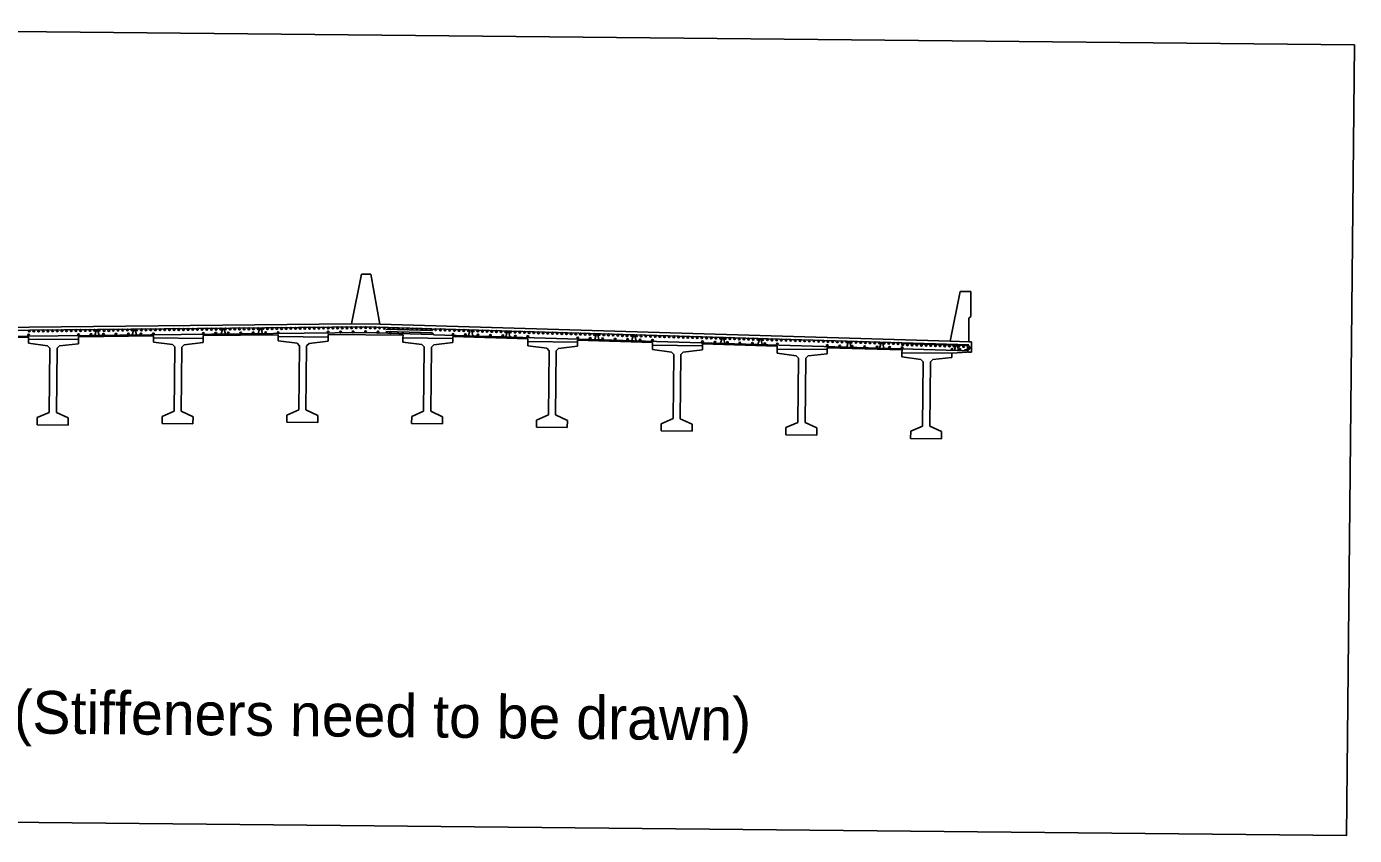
# Model space of a CAD drawing. Extents: x 632228 to 632434, y 378391 to 382112.
# Drawn here: x 632303.6 to 632396.7, y 378390.6 to 378447.3 of the extents above; entities that cross this region are included whole.
import ezdxf

# ---------------------------------------------------------------- set-up
doc = ezdxf.new("R2010")
doc.units = 0
for name, color, linetype in [('B_Boring Annot', 7, 'Continuous'), ('R_Border_Divider', 7, 'Continuous'), ('R_Border_Scale', 7, 'Continuous'), ('USACE_Easement', 7, 'Continuous')]:
    doc.layers.add(name, color=color, linetype=linetype)

msp = doc.modelspace()

# ---------------------------------------------------------------- linework, layer by layer
at = {"layer": 'B_Boring Annot'}
for p, q in [((632326.34, 378426.46), (632327.042, 378429.953)), ((632327.042, 378429.953), (632327.708, 378429.947)), ((632327.708, 378429.947), (632327.042, 378429.953)), ((632328.34, 378426.44), (632327.708, 378429.947)), ((632369.032, 378428.736), (632368.33, 378425.242)), ((632369.782, 378428.728), (632369.032, 378428.736)), ((632369.764, 378426.978), (632369.782, 378428.728)), ((632326.34, 378426.46), (632286.334, 378426.058)), ((632328.34, 378426.44), (632368.33, 378425.242)), ((632369.622, 378425.204), (632369.638, 378426.855)), ((632369.764, 378426.978), (632369.638, 378426.855)), ((632303.705, 378425.524), (632298.454, 378425.471)), ((632303.705, 378425.524), (632303.704, 378425.392)), ((632307.206, 378425.559), (632307.204, 378425.358)), ((632312.456, 378425.612), (632307.206, 378425.559)), ((632312.452, 378425.189), (632312.455, 378425.48)), ((632312.456, 378425.612), (632312.455, 378425.48)), ((632312.455, 378425.48), (632315.955, 378425.446)), ((632315.957, 378425.647), (632315.955, 378425.446)), ((632321.208, 378425.7), (632315.957, 378425.647)), ((632321.203, 378425.277), (632321.206, 378425.568)), ((632321.206, 378425.568), (632321.208, 378425.7)), ((632321.206, 378425.568), (632324.706, 378425.534)), ((632324.706, 378425.534), (632321.206, 378425.568)), ((632324.706, 378425.534), (632324.703, 378425.242)), ((632324.708, 378425.71), (632324.706, 378425.534)), ((632324.708, 378425.71), (632329.958, 378425.658)), ((632329.956, 378425.481), (632329.953, 378425.19)), ((632329.958, 378425.658), (632329.956, 378425.481)), ((632333.456, 378425.447), (632329.956, 378425.481)), ((632329.956, 378425.481), (632333.456, 378425.447)), ((632333.456, 378425.447), (632333.457, 378425.578)), ((632333.457, 378425.578), (632338.706, 378425.421)), ((632303.701, 378425.101), (632303.704, 378425.392)), ((632305.032, 378424.921), (632303.701, 378425.101)), ((632303.704, 378425.392), (632307.204, 378425.358)), ((632305.197, 378424.752), (632305.032, 378424.921)), ((632305.153, 378420.253), (632305.197, 378424.752)), ((632305.697, 378424.748), (632305.653, 378420.248)), ((632305.866, 378424.913), (632305.697, 378424.748)), ((632307.201, 378425.066), (632305.866, 378424.913)), ((632307.204, 378425.358), (632307.201, 378425.066)), ((632313.784, 378425.009), (632312.452, 378425.189)), ((632313.949, 378424.84), (632313.784, 378425.009)), ((632313.904, 378420.341), (632313.949, 378424.84)), ((632314.449, 378424.836), (632314.404, 378420.336)), ((632314.617, 378425.001), (632314.449, 378424.836)), ((632315.952, 378425.154), (632314.617, 378425.001)), ((632315.955, 378425.446), (632315.952, 378425.154)), ((632322.535, 378425.097), (632321.203, 378425.277)), ((632322.7, 378424.928), (632322.535, 378425.097)), ((632322.655, 378420.429), (632322.7, 378424.928)), ((632323.2, 378424.924), (632323.155, 378420.424)), ((632323.368, 378425.089), (632323.2, 378424.924)), ((632324.703, 378425.242), (632323.368, 378425.089)), ((632329.953, 378425.19), (632331.285, 378425.01)), ((632331.285, 378425.01), (632331.45, 378424.841)), ((632331.45, 378424.841), (632331.405, 378420.342)), ((632331.905, 378420.337), (632331.95, 378424.837)), ((632331.95, 378424.837), (632332.118, 378425.002)), ((632332.118, 378425.002), (632333.453, 378425.155)), ((632333.453, 378425.155), (632333.456, 378425.447)), ((632338.704, 378425.219), (632338.701, 378424.928)), ((632338.701, 378424.928), (632340.032, 378424.748)), ((632338.706, 378425.421), (632338.704, 378425.219)), ((632342.204, 378425.185), (632338.704, 378425.219)), ((632340.032, 378424.748), (632340.197, 378424.579)), ((632340.197, 378424.579), (632340.153, 378420.08)), ((632340.653, 378420.075), (632340.697, 378424.575)), ((632340.697, 378424.575), (632340.866, 378424.74)), ((632340.866, 378424.74), (632342.201, 378424.893)), ((632342.201, 378424.893), (632342.204, 378425.185)), ((632342.205, 378425.316), (632342.204, 378425.185)), ((632342.205, 378425.316), (632347.454, 378425.159)), ((632347.452, 378424.957), (632347.449, 378424.666)), ((632347.449, 378424.666), (632348.78, 378424.486)), ((632347.454, 378425.159), (632347.452, 378424.957)), ((632350.951, 378424.923), (632347.452, 378424.957)), ((632349.614, 378424.478), (632350.948, 378424.631)), ((632350.948, 378424.631), (632350.951, 378424.923)), ((632350.953, 378425.054), (632350.951, 378424.923)), ((632350.953, 378425.054), (632356.201, 378424.897)), ((632356.199, 378424.695), (632356.196, 378424.404)), ((632356.201, 378424.897), (632356.199, 378424.695)), ((632359.699, 378424.661), (632356.199, 378424.695)), ((632359.696, 378424.369), (632359.699, 378424.661)), ((632359.7, 378424.792), (632359.699, 378424.661)), ((632359.7, 378424.792), (632364.949, 378424.635)), ((632364.949, 378424.635), (632364.947, 378424.433)), ((632369.622, 378425.204), (632369.83, 378425.198)), ((632369.83, 378425.198), (632369.823, 378424.489)), ((632348.78, 378424.486), (632348.945, 378424.318)), ((632348.945, 378424.318), (632348.9, 378419.818)), ((632349.4, 378419.813), (632349.445, 378424.313)), ((632349.445, 378424.313), (632349.614, 378424.478)), ((632356.196, 378424.404), (632357.528, 378424.224)), ((632357.528, 378424.224), (632357.693, 378424.056)), ((632357.693, 378424.056), (632357.648, 378419.556)), ((632358.148, 378419.551), (632358.193, 378424.051)), ((632358.193, 378424.051), (632358.361, 378424.216)), ((632358.361, 378424.216), (632359.696, 378424.369)), ((632364.947, 378424.433), (632364.944, 378424.142)), ((632364.944, 378424.142), (632366.276, 378423.962)), ((632368.447, 378424.399), (632364.947, 378424.433)), ((632366.276, 378423.962), (632366.441, 378423.794)), ((632366.441, 378423.794), (632366.396, 378419.294)), ((632366.896, 378419.289), (632366.941, 378423.789)), ((632366.941, 378423.789), (632367.109, 378423.954)), ((632367.109, 378423.954), (632368.444, 378424.107)), ((632368.444, 378424.107), (632368.447, 378424.399)), ((632368.447, 378424.399), (632369.537, 378424.47)), ((632369.537, 378424.47), (632369.573, 378424.515)), ((632369.622, 378424.476), (632369.573, 378424.515)), ((632369.622, 378424.476), (632369.823, 378424.489)), ((632304.311, 378419.386), (632304.316, 378419.886)), ((632304.316, 378419.886), (632305.153, 378420.253)), ((632305.653, 378420.248), (632306.482, 378419.864)), ((632306.482, 378419.864), (632306.477, 378419.364)), ((632313.062, 378419.474), (632313.067, 378419.974)), ((632313.067, 378419.974), (632313.904, 378420.341)), ((632314.404, 378420.336), (632315.234, 378419.952)), ((632315.234, 378419.952), (632315.229, 378419.452)), ((632321.813, 378419.562), (632321.818, 378420.062)), ((632321.818, 378420.062), (632322.655, 378420.429)), ((632323.155, 378420.424), (632323.985, 378420.04)), ((632323.985, 378420.04), (632323.98, 378419.54)), ((632330.568, 378419.975), (632330.563, 378419.475)), ((632331.405, 378420.342), (632330.568, 378419.975)), ((632332.734, 378419.953), (632331.905, 378420.337)), ((632332.729, 378419.453), (632332.734, 378419.953)), ((632340.153, 378420.08), (632339.316, 378419.713)), ((632341.482, 378419.691), (632340.653, 378420.075)), ((632306.477, 378419.364), (632304.311, 378419.386)), ((632315.229, 378419.452), (632313.062, 378419.474)), ((632323.98, 378419.54), (632321.813, 378419.562)), ((632330.563, 378419.475), (632332.729, 378419.453)), ((632339.316, 378419.713), (632339.311, 378419.213)), ((632339.311, 378419.213), (632341.477, 378419.192)), ((632341.477, 378419.192), (632341.482, 378419.691)), ((632348.063, 378419.451), (632348.059, 378418.951)), ((632348.059, 378418.951), (632350.225, 378418.93)), ((632348.9, 378419.818), (632348.063, 378419.451)), ((632350.23, 378419.43), (632349.4, 378419.813)), ((632350.225, 378418.93), (632350.23, 378419.43)), ((632356.811, 378419.189), (632356.806, 378418.689)), ((632357.648, 378419.556), (632356.811, 378419.189)), ((632358.978, 378419.168), (632358.148, 378419.551)), ((632358.973, 378418.668), (632358.978, 378419.168)), ((632366.396, 378419.294), (632365.559, 378418.927)), ((632367.726, 378418.906), (632366.896, 378419.289)), ((632356.806, 378418.689), (632358.973, 378418.668)), ((632365.559, 378418.927), (632365.554, 378418.427)), ((632365.554, 378418.427), (632367.721, 378418.406)), ((632367.721, 378418.406), (632367.726, 378418.906))]:
    msp.add_line(p, q, dxfattribs=at)
at = {"layer": 'R_Border_Divider'}
for p, q in [((632326.34, 378426.46), (632328.34, 378426.44)), ((632368.33, 378425.242), (632369.622, 378425.204))]:
    msp.add_line(p, q, dxfattribs=at)
at = {"layer": 'R_Border_Scale'}
for p, q in [((632285.03, 378425.837), (632327.339, 378426.262)), ((632285.038, 378425.42), (632327.334, 378425.845)), ((632308.468, 378426.072), (632308.36, 378425.654)), ((632308.542, 378426.073), (632308.657, 378425.657)), ((632311.074, 378426.099), (632310.966, 378425.68)), ((632311.148, 378426.099), (632311.264, 378425.683)), ((632317.313, 378426.161), (632317.205, 378425.743)), ((632317.387, 378426.162), (632317.502, 378425.746)), ((632319.921, 378426.188), (632319.813, 378425.769)), ((632319.995, 378426.188), (632320.111, 378425.772)), ((632332, 378425.705), (632327.334, 378425.845)), ((632332.004, 378426.122), (632327.339, 378426.262)), ((632332.001, 378425.83), (632328.752, 378425.928)), ((632332.003, 378425.997), (632328.754, 378426.095)), ((632332.001, 378425.83), (632332.122, 378425.702)), ((632332.003, 378425.997), (632332.131, 378426.119)), ((632369.614, 378424.579), (632332.122, 378425.702)), ((632369.63, 378424.996), (632332.131, 378426.119)), ((632334.679, 378426.042), (632334.555, 378425.629)), ((632334.753, 378426.04), (632334.852, 378425.62)), ((632337.286, 378425.964), (632337.162, 378425.551)), ((632337.36, 378425.962), (632337.46, 378425.542)), ((632343.523, 378425.777), (632343.399, 378425.364)), ((632343.597, 378425.775), (632343.696, 378425.355)), ((632346.128, 378425.699), (632346.004, 378425.286)), ((632346.202, 378425.697), (632346.301, 378425.277)), ((632352.353, 378425.513), (632352.229, 378425.099)), ((632352.427, 378425.511), (632352.527, 378425.091)), ((632354.968, 378425.435), (632354.844, 378425.021)), ((632355.042, 378425.432), (632355.141, 378425.012)), ((632361.199, 378425.248), (632361.075, 378424.835)), ((632361.273, 378425.246), (632361.372, 378424.826)), ((632363.504, 378425.179), (632363.38, 378424.766)), ((632363.578, 378425.177), (632363.678, 378424.757)), ((632369.573, 378424.936), (632364.897, 378425.075)), ((632368.742, 378425.022), (632368.618, 378424.609)), ((632368.816, 378425.02), (632368.915, 378424.6)), ((632369.564, 378424.643), (632369.335, 378424.65))]:
    msp.add_line(p, q, dxfattribs=at)
for centre in [(632303.703, 378425.67), (632303.75, 378425.962), (632304.076, 378425.966), (632304.404, 378425.969), (632304.733, 378425.972), (632305.059, 378425.976), (632305.387, 378425.979), (632305.716, 378425.982), (632306.042, 378425.986), (632306.37, 378425.989), (632306.698, 378425.992), (632307.022, 378425.995), (632307.206, 378425.705), (632307.35, 378425.999), (632307.681, 378426.002), (632308.008, 378426.005), (632308.079, 378425.714), (632308.335, 378426.009), (632308.664, 378426.012), (632308.954, 378425.723), (632309, 378425.993), (632309.327, 378425.996), (632309.647, 378426.022), (632309.829, 378425.732), (632309.973, 378426.025), (632310.301, 378426.028), (632310.63, 378426.032), (632310.704, 378425.74), (632310.956, 378426.035), (632311.284, 378426.038), (632311.579, 378425.749), (632311.613, 378426.041), (632311.939, 378426.045), (632312.267, 378426.048), (632312.454, 378425.758), (632312.595, 378426.051), (632312.922, 378426.055), (632313.249, 378426.058), (632313.578, 378426.061), (632313.905, 378426.065), (632314.232, 378426.068), (632314.561, 378426.071), (632314.888, 378426.074), (632315.215, 378426.078), (632315.544, 378426.081), (632315.87, 378426.084), (632315.957, 378425.793), (632316.198, 378426.088), (632316.527, 378426.091), (632316.831, 378425.802), (632316.853, 378426.094), (632317.181, 378426.098), (632317.51, 378426.101), (632317.706, 378425.811), (632317.836, 378426.104), (632318.164, 378426.107), (632318.493, 378426.111), (632318.581, 378425.82), (632318.819, 378426.114), (632319.147, 378426.117), (632319.455, 378425.828), (632319.471, 378426.121), (632319.798, 378426.124), (632320.125, 378426.127), (632320.33, 378425.837), (632320.458, 378426.13), (632320.785, 378426.134), (632321.112, 378426.137), (632321.205, 378425.846), (632321.441, 378426.14), (632321.765, 378426.144), (632322.093, 378426.147), (632322.424, 378426.15), (632322.75, 378426.154), (632323.078, 378426.157), (632323.407, 378426.16), (632323.733, 378426.163), (632324.061, 378426.167), (632324.39, 378426.17), (632324.71, 378425.881), (632324.716, 378426.173), (632325.044, 378426.177), (632325.372, 378426.18), (632325.584, 378425.89), (632325.699, 378426.183), (632326.026, 378426.186), (632326.355, 378426.19), (632326.459, 378425.899), (632326.682, 378426.193), (632327.009, 378426.196), (632327.334, 378425.908), (632327.338, 378426.2), (632327.666, 378426.19), (632327.994, 378426.18), (632328.211, 378425.881), (632328.32, 378426.17), (632328.649, 378426.16), (632328.976, 378426.151), (632329.085, 378425.855), (632329.303, 378426.141), (632329.631, 378426.131), (632329.959, 378426.121), (632329.959, 378425.829), (632330.285, 378426.111), (632330.614, 378426.102), (632330.941, 378426.092), (632331.267, 378426.082), (632331.596, 378426.072), (632331.924, 378426.062), (632332.25, 378426.053), (632332.581, 378426.043), (632332.909, 378426.033), (632333.232, 378426.023), (632333.462, 378425.724), (632333.561, 378426.013), (632333.888, 378426.003), (632334.215, 378425.994), (632334.337, 378425.698), (632334.548, 378425.984), (632334.875, 378425.974), (632335.201, 378425.964), (632335.211, 378425.672), (632335.526, 378425.954), (632335.853, 378425.945), (632336.086, 378425.645), (632336.18, 378425.935), (632336.508, 378425.925), (632336.836, 378425.915), (632336.961, 378425.619), (632337.162, 378425.905), (632337.491, 378425.896), (632337.818, 378425.886), (632337.835, 378425.593), (632338.145, 378425.876), (632338.473, 378425.866), (632338.708, 378425.567), (632338.801, 378425.856), (632339.127, 378425.847), (632339.456, 378425.837), (632339.783, 378425.827), (632340.11, 378425.817), (632340.438, 378425.807), (632340.766, 378425.798), (632341.092, 378425.788), (632341.421, 378425.778), (632341.748, 378425.768), (632342.074, 378425.758), (632342.21, 378425.462), (632342.403, 378425.748), (632342.731, 378425.739), (632343.057, 378425.729), (632343.085, 378425.436), (632343.386, 378425.719), (632343.713, 378425.709), (632343.959, 378425.41), (632344.039, 378425.699), (632344.368, 378425.69), (632344.696, 378425.68), (632345.022, 378425.67), (632345.341, 378425.638), (632345.668, 378425.628), (632346.004, 378425.641), (632346.333, 378425.631), (632346.66, 378425.621), (632346.987, 378425.611), (632347.318, 378425.601), (632347.645, 378425.591), (632347.969, 378425.582), (632348.298, 378425.572), (632348.625, 378425.562), (632348.952, 378425.552), (632349.28, 378425.543), (632349.608, 378425.533), (632349.934, 378425.523), (632350.263, 378425.513), (632350.59, 378425.503), (632350.917, 378425.493), (632351.245, 378425.484), (632351.573, 378425.474), (632351.899, 378425.464), (632352.228, 378425.454), (632352.555, 378425.444), (632352.881, 378425.435), (632353.21, 378425.425), (632353.538, 378425.415), (632353.864, 378425.405), (632354.193, 378425.395), (632344.834, 378425.384), (632345.708, 378425.357), (632346.583, 378425.331), (632347.456, 378425.305), (632350.958, 378425.2), (632351.832, 378425.174), (632352.707, 378425.148), (632353.582, 378425.122), (632354.456, 378425.095), (632354.52, 378425.386), (632354.846, 378425.376), (632355.175, 378425.366), (632355.331, 378425.069), (632355.503, 378425.356), (632355.829, 378425.346), (632356.158, 378425.337), (632356.204, 378425.043), (632356.485, 378425.327), (632356.811, 378425.317), (632357.14, 378425.307), (632357.467, 378425.297), (632357.794, 378425.288), (632358.122, 378425.278), (632358.45, 378425.268), (632358.776, 378425.258), (632359.105, 378425.248), (632359.432, 378425.238), (632359.706, 378424.938), (632359.759, 378425.229), (632360.087, 378425.219), (632360.415, 378425.209), (632360.58, 378424.912), (632360.741, 378425.199), (632361.07, 378425.189), (632361.397, 378425.18), (632361.455, 378424.886), (632361.724, 378425.17), (632362.052, 378425.16), (632362.329, 378424.86), (632362.38, 378425.15), (632362.706, 378425.14), (632363.035, 378425.131), (632363.204, 378424.833), (632363.362, 378425.121), (632363.688, 378425.111), (632364.017, 378425.101), (632364.079, 378424.807), (632364.345, 378425.091), (632364.671, 378425.082), (632364.952, 378424.781), (632364.999, 378425.009), (632365.326, 378425), (632365.653, 378424.99), (632365.982, 378424.98), (632366.309, 378424.971), (632366.635, 378424.961), (632366.964, 378424.951), (632367.291, 378424.942), (632367.618, 378424.932), (632367.946, 378424.922), (632368.274, 378424.912), (632368.451, 378424.676), (632368.6, 378424.903), (632368.939, 378424.893), (632369.015, 378424.659), (632369.266, 378424.883), (632369.583, 378424.874), (632369.583, 378424.706)]:
    msp.add_circle(centre, 0.0625, dxfattribs=at)
msp.add_arc((632369.568, 378424.79), 0.147, 268.28459, 88.2846, dxfattribs=at)
at = {"layer": 'USACE_Easement'}
msp.add_lwpolyline([(632267.311, 378447.311), (632396.672, 378446.025), (632396.121, 378390.588), (632266.759, 378391.874)], close=True, dxfattribs=at)

# ---------------------------------------------------------------- texts
at = {"layer": 'R_Border_Divider'}
msp.add_text('0.0000', height=0.005, rotation=359.43036, dxfattribs=at).set_placement((632315.203, 378427.717))
at = {"layer": 'USACE_Easement'}
msp.add_text('Bridge 01 unit 1 (Stiffeners need to be drawn)', height=3, rotation=359.43036, dxfattribs=at).set_placement((632273.409, 378398.037))

doc.saveas('drawing.dxf')
